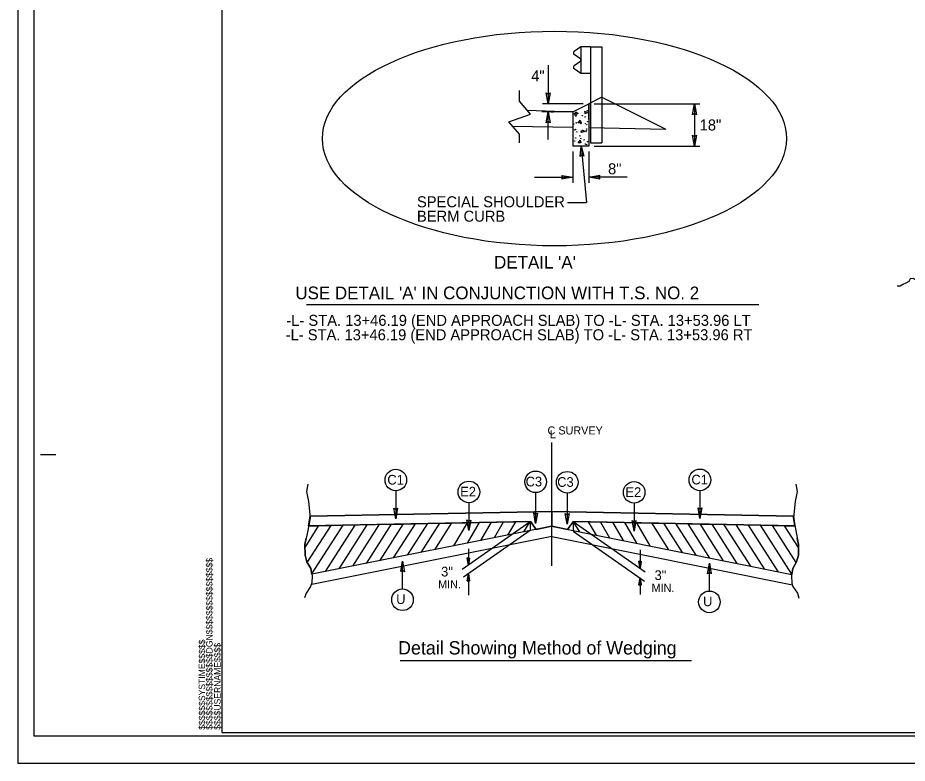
# Model space of a CAD drawing. Extents: x 573711 to 575883, y -54585 to -53485.
# Drawn here: x 573711 to 574439, y -54585 to -53975 of the extents above; entities that cross this region are included whole.
import ezdxf

# ---------------------------------------------------------------- set-up
doc = ezdxf.new("R2010")
doc.units = 0
for name, color, linetype in [('Old_Level_1', 7, 'Continuous'), ('Old_Level_11', 7, 'Continuous'), ('Old_Level_20', 7, 'Continuous'), ('Old_Level_21', 7, 'Continuous'), ('Prop Dimension', 7, 'Continuous'), ('Prop Shade Medium', 7, 'Continuous'), ('Prop Terminator CELL', 7, 'Continuous'), ('Sheet Cutting Line CELL', 7, 'Continuous'), ('Sheet Plot Border Inside CELL', 7, 'Continuous'), ('Sheet Plot Border Outside CELL', 7, 'Continuous'), ('Sheet Typical CELL', 7, 'Continuous'), ('Typical Curb CELL', 7, 'Continuous'), ('Typical Guardrail CELL', 7, 'Continuous'), ('Typical Pavement Slope CELL', 7, 'Continuous'), ('Typical Terminator CELL', 7, 'Continuous'), ('Typical Text Asphalt at Bridge Approach CELL', 7, 'Continuous'), ('Typical Text General CELL', 7, 'Continuous'), ('Typical Text Label CELL', 7, 'Continuous')]:
    doc.layers.add(name, color=color, linetype=linetype)

msp = doc.modelspace()

# ---------------------------------------------------------------- linework, layer by layer
at = {"layer": 'Old_Level_1'}
for p, q in [((574145.08, -54014.19), (574145.08, -54045.69)), ((574173.79, -54045.69), (574140.58, -54045.69)), ((574178.29, -54045.69), (574178.29, -54080.26)), ((574182.79, -54045.69), (574269.3, -54045.69)), ((574264.8, -54045.69), (574264.8, -54080.26)), ((574165.39, -54052.14), (574139.8, -54052.14)), ((574145.08, -54074.83), (574145.08, -54052.14)), ((574147.57, -54052.14), (574149.58, -54052.14)), ((574165.39, -54052.14), (574165.39, -54080.26)), ((574165.39, -54084.76), (574165.39, -54110.24)), ((574178.29, -54084.76), (574178.29, -54110.24)), ((574182.79, -54080.26), (574269.3, -54080.26)), ((574133.89, -54105.74), (574165.39, -54105.74)), ((574209.79, -54105.74), (574178.29, -54105.74)), ((574148.08, -54423.57), (574148.09, -54322.78)), ((574078.84, -54388.35), (574067.76, -54407.32)), ((574088.71, -54388.14), (574078.83, -54405.11)), ((574098.48, -54387.95), (574089.75, -54402.92)), ((574108.33, -54387.98), (574100.9, -54400.69)), ((574118.26, -54387.47), (574111.81, -54398.51)), ((574165.69, -54387.39), (574224.51, -54428.59)), ((574177.89, -54387.48), (574184.34, -54398.52)), ((574187.82, -54387.98), (574195.25, -54400.7)), ((574197.67, -54387.96), (574206.41, -54402.94)), ((574207.44, -54388.15), (574217.33, -54405.12)), ((574217.32, -54388.36), (574228.39, -54407.34)), ((574148, -54399.67), (573951.67, -54438.92)), ((574130.47, -54394.78), (574075.92, -54432.96)), ((574148.15, -54399.67), (574344.92, -54439.05)), ((574165.69, -54395.26), (574223.87, -54436)), ((574079.83, -54409.67), (574079.83, -54422.93)), ((574220.31, -54410.44), (574220.31, -54425.64)), ((574079.83, -54422.93), (574078.81, -54417.11)), ((574079.83, -54417.87), (574078.81, -54417.11)), ((574079.83, -54422.93), (574078.95, -54417.22)), ((574079.1, -54417.33), (574079.83, -54422.93)), ((574079.83, -54422.93), (574079.25, -54417.43)), ((574079.4, -54417.54), (574079.83, -54422.93)), ((574079.83, -54422.93), (574079.54, -54417.65)), ((574079.69, -54417.76), (574079.83, -54422.93)), ((574079.83, -54422.93), (574080.87, -54417.11)), ((574080.87, -54417.11), (574079.83, -54417.87)), ((574080.72, -54417.22), (574079.83, -54422.93)), ((574079.83, -54422.93), (574080.56, -54417.33)), ((574080.42, -54417.43), (574079.83, -54422.93)), ((574079.83, -54422.93), (574080.27, -54417.54)), ((574080.12, -54417.65), (574079.83, -54422.93)), ((574079.83, -54422.93), (574079.98, -54417.76)), ((574079.83, -54417.87), (574079.83, -54422.93)), ((574220.31, -54425.64), (574219.29, -54419.83)), ((574220.31, -54420.58), (574219.29, -54419.83)), ((574220.31, -54425.64), (574219.43, -54419.93)), ((574219.58, -54420.04), (574220.31, -54425.64)), ((574220.31, -54425.64), (574219.72, -54420.15)), ((574219.87, -54420.26), (574220.31, -54425.64)), ((574220.31, -54425.64), (574220.01, -54420.36)), ((574220.16, -54420.47), (574220.31, -54425.64)), ((574220.31, -54425.64), (574221.34, -54419.83)), ((574221.34, -54419.83), (574220.31, -54420.58)), ((574221.18, -54419.93), (574220.31, -54425.64)), ((574220.31, -54425.64), (574221.04, -54420.04)), ((574220.89, -54420.15), (574220.31, -54425.64)), ((574220.31, -54425.64), (574220.75, -54420.26)), ((574220.6, -54420.36), (574220.31, -54425.64)), ((574220.31, -54425.64), (574220.46, -54420.47)), ((574220.31, -54420.58), (574220.31, -54425.64)), ((574079.83, -54430.23), (574078.81, -54436.04)), ((574078.81, -54436.04), (574079.83, -54435.29)), ((574078.95, -54435.93), (574079.83, -54430.23)), ((574079.83, -54430.23), (574079.1, -54435.83)), ((574079.24, -54435.71), (574079.83, -54430.23)), ((574079.83, -54430.23), (574079.4, -54435.61)), ((574079.54, -54435.51), (574079.83, -54430.23)), ((574079.83, -54430.23), (574079.69, -54435.4)), ((574079.83, -54430.23), (574079.83, -54447.48)), ((574079.83, -54430.23), (574080.86, -54436.04)), ((574079.83, -54435.29), (574079.83, -54430.23)), ((574079.98, -54435.4), (574079.83, -54430.23)), ((574079.83, -54430.23), (574080.12, -54435.51)), ((574080.27, -54435.61), (574079.83, -54430.23)), ((574079.83, -54430.23), (574080.41, -54435.71)), ((574080.56, -54435.83), (574079.83, -54430.23)), ((574079.83, -54430.23), (574080.72, -54435.93)), ((574079.83, -54435.29), (574080.86, -54436.04)), ((574220.31, -54433.51), (574219.28, -54439.33)), ((574219.43, -54439.21), (574220.31, -54433.51)), ((574220.31, -54433.51), (574219.57, -54439.11)), ((574219.72, -54439), (574220.31, -54433.51)), ((574220.31, -54433.51), (574219.87, -54438.89)), ((574220.01, -54438.79), (574220.31, -54433.51)), ((574220.31, -54433.51), (574220.16, -54438.68)), ((574220.31, -54433.51), (574220.31, -54447.11)), ((574220.31, -54433.51), (574221.33, -54439.33)), ((574220.31, -54438.57), (574220.31, -54433.51)), ((574220.45, -54438.68), (574220.31, -54433.51)), ((574220.31, -54433.51), (574220.6, -54438.79)), ((574220.75, -54438.89), (574220.31, -54433.51)), ((574220.31, -54433.51), (574220.89, -54439)), ((574221.04, -54439.11), (574220.31, -54433.51)), ((574220.31, -54433.51), (574221.18, -54439.21)), ((574219.28, -54439.33), (574220.31, -54438.57)), ((574220.31, -54438.57), (574221.33, -54439.33))]:
    msp.add_line(p, q, dxfattribs=at)
for points in [[(574469.08, -54191.1), (574459.47, -54192.29), (574457.07, -54192.29), (574453.46, -54192.29), (574451.05, -54192.29), (574448.65, -54191.1), (574446.25, -54189.89), (574443.84, -54188.68), (574441.44, -54188.69), (574440.24, -54191.1), (574437.83, -54192.3), (574435.43, -54193.5), (574433.03, -54194.7), (574430.62, -54194.7)], [(573948.42, -54356.87), (573947.37, -54362.66), (573948.95, -54370.9), (573950.35, -54384.24), (573948.42, -54394.77), (573946.14, -54406.17), (573946.32, -54414.77), (573947.72, -54420.21), (573950.88, -54425.65), (573951.93, -54431.62), (573951.75, -54437.58), (573950.7, -54440.39), (573947.02, -54446.01), (573945.79, -54449.87)], [(574347.73, -54356.9), (574348.79, -54362.7), (574347.21, -54370.94), (574345.8, -54384.28), (574347.73, -54394.81), (574350.01, -54406.21), (574349.84, -54414.81), (574348.42, -54420.24), (574345.27, -54425.69), (574344.22, -54431.65), (574344.39, -54437.62), (574345.44, -54440.43), (574349.12, -54446.05), (574350.35, -54449.91)], [(573946.19, -54408.47), (573957.58, -54390.7)], [(573948.04, -54420.75), (573967.42, -54390.5)], [(573951.68, -54430.22), (573977.25, -54390.31)], [(573962.93, -54428.28), (573987.23, -54390.35)], [(573974.06, -54426.06), (573997.07, -54390.15)], [(573985.2, -54423.83), (574006.9, -54389.96)], [(573996.36, -54421.6), (574016.94, -54389.49)], [(574007.5, -54419.37), (574026.78, -54389.29)], [(574018.64, -54417.14), (574036.62, -54389.09)], [(574030.03, -54414.87), (574046.69, -54388.88)], [(574041.17, -54412.64), (574056.52, -54388.68)], [(574052.31, -54410.41), (574066.36, -54388.48)], [(574243.85, -54410.43), (574229.8, -54388.5)], [(574254.99, -54412.66), (574239.64, -54388.7)], [(574266.13, -54414.89), (574249.47, -54388.9)], [(574277.51, -54417.17), (574259.54, -54389.11)], [(574288.65, -54419.4), (574269.38, -54389.31)], [(574299.79, -54421.63), (574279.22, -54389.51)], [(574310.94, -54423.86), (574289.24, -54389.99)], [(574322.08, -54426.09), (574299.08, -54390.18)], [(574333.22, -54428.32), (574308.92, -54390.38)], [(574344.46, -54430.26), (574318.89, -54390.34)], [(574348.11, -54420.79), (574328.73, -54390.53)], [(574349.96, -54408.52), (574338.57, -54390.73)], [(573951.73, -54430.52), (573950.88, -54425.65), (573947.72, -54420.21), (573946.32, -54414.77), (573946.14, -54406.17), (573947.2, -54400.89)], [(574344.41, -54430.56), (574345.27, -54425.69), (574348.42, -54420.24), (574349.84, -54414.81), (574350.01, -54406.21), (574348.95, -54400.92)]]:
    msp.add_lwpolyline(points, dxfattribs=at)
msp.add_ellipse((574150.25, -54074.07), major_axis=(189.85, 0), ratio=0.462267, dxfattribs=at)
at = {"layer": 'Old_Level_11'}
for p, q in [((574020.45, -54362.22), (574020.45, -54385.06)), ((574134.86, -54363.71), (574134.85, -54389.04)), ((574269.29, -54362.1), (574269.28, -54384.93)), ((574160.7, -54364.06), (574160.7, -54389.4)), ((574080.24, -54371.96), (574080.24, -54394.8)), ((574215.46, -54372.32), (574215.46, -54395.15)), ((573949.13, -54390.92), (573950.26, -54382.97)), ((574148.07, -54379.04), (573950.26, -54382.97)), ((573950.26, -54382.97), (574148.07, -54379.04)), ((574148.07, -54379.04), (574345.9, -54383.01)), ((574148.09, -54379.04), (574345.9, -54383.01)), ((574345.9, -54383.01), (574347.03, -54390.96)), ((574130.72, -54387.31), (573949.13, -54390.92)), ((574130.72, -54387.31), (573949.13, -54390.92)), ((574148.37, -54391.2), (573951.74, -54430.52)), ((574130.49, -54387.46), (574074.76, -54426.49)), ((574125.1, -54395.77), (574130.47, -54387.38)), ((574130.47, -54387.38), (574130.47, -54394.78)), ((574135.16, -54393.83), (574130.72, -54387.31)), ((574130.72, -54387.52), (574135.16, -54393.83)), ((574147.78, -54391.2), (574135.16, -54393.83)), ((574147.78, -54391.2), (574344.41, -54430.56)), ((574160.99, -54393.83), (574147.78, -54391.2)), ((574165.58, -54387.31), (574160.99, -54393.83)), ((574165.58, -54387.31), (574160.99, -54393.83)), ((574165.28, -54387.46), (574165.57, -54387.47)), ((574165.58, -54387.31), (574347.03, -54390.96)), ((574347.03, -54390.96), (574165.58, -54387.31)), ((574171.06, -54395.77), (574165.69, -54387.39)), ((574165.69, -54387.39), (574165.69, -54394.79)), ((574025.92, -54442.47), (574025.93, -54419.63)), ((574277.02, -54444.26), (574277.03, -54421.42)), ((574262.32, -54501.4), (574024.05, -54501.37))]:
    msp.add_line(p, q, dxfattribs=at)
for points in [[(574021.95, -54376.37), (574020.45, -54385.06), (574018.9, -54376.32), (574020.45, -54377.43)], [(574270.78, -54376.25), (574269.28, -54384.93), (574267.74, -54376.2), (574269.28, -54377.31)], [(574136.35, -54380.36), (574134.85, -54389.04), (574133.31, -54380.31), (574134.85, -54381.42)], [(574162.2, -54380.71), (574160.7, -54389.4), (574159.15, -54380.66), (574160.7, -54381.77)], [(574081.74, -54386.11), (574080.24, -54394.8), (574078.69, -54386.06), (574080.24, -54387.17)], [(574216.95, -54386.47), (574215.46, -54395.15), (574213.91, -54386.42), (574215.46, -54387.53)], [(574024.43, -54428.32), (574025.93, -54419.63), (574027.47, -54428.37), (574025.93, -54427.26)], [(574275.53, -54430.11), (574277.03, -54421.42), (574278.57, -54430.16), (574277.03, -54429.05)]]:
    msp.add_lwpolyline(points, close=True, dxfattribs=at)
for centre in [(574020.45, -54353.39), (574134.86, -54354.87), (574160.7, -54355.22), (574269.28, -54353.27), (574080.24, -54363.13), (574215.46, -54363.48), (574025.92, -54451.3), (574277.02, -54453.09)]:
    msp.add_circle(centre, 8.84, dxfattribs=at)
at = {"layer": 'Prop Dimension'}
for p in [(574172.01, -54080.26), (574160.82, -54126.44)]:
    msp.add_line(p, (574176.51, -54126.44), dxfattribs=at)
at = {"layer": 'Prop Shade Medium'}
for points in [[(574066.29, -54388.59), (574088.71, -54388.15), (574118.2, -54387.56), (574130.72, -54387.31), (574135.16, -54393.83), (574147.78, -54391.2), (574148.08, -54391.26), (574148.08, -54391.26), (574148.08, -54379.04), (574148.07, -54379.04), (573950.26, -54382.97), (573950.24, -54383.16), (573950.35, -54384.24), (573949.16, -54390.72), (573949.13, -54390.92), (573957.54, -54390.76), (573967.38, -54390.56), (573977.22, -54390.36), (574016.89, -54389.57), (574026.72, -54389.38), (574036.56, -54389.18), (574046.62, -54388.98), (574056.45, -54388.79), (574066.29, -54388.59)], [(574229.87, -54388.61), (574239.7, -54388.8), (574249.54, -54389), (574259.6, -54389.2), (574269.44, -54389.4), (574279.27, -54389.6), (574318.93, -54390.39), (574328.77, -54390.59), (574338.61, -54390.79), (574347.02, -54390.96), (574345.8, -54384.28), (574345.92, -54383.17), (574345.9, -54383.01), (574148.09, -54379.04), (574148.08, -54379.04), (574148.08, -54391.26), (574148.08, -54391.26), (574160.99, -54393.83), (574165.47, -54387.47), (574165.58, -54387.31), (574177.95, -54387.56), (574207.44, -54388.15), (574207.44, -54388.15), (574207.44, -54388.15), (574229.87, -54388.61)]]:
    msp.add_lwpolyline(points, dxfattribs=at)
at = {"layer": 'Prop Terminator CELL'}
for points in [[(574146.63, -54036.69), (574145.08, -54045.69), (574143.48, -54036.64), (574145.08, -54037.79)], [(574263.25, -54054.69), (574264.8, -54045.69), (574266.4, -54054.74), (574264.8, -54053.59)], [(574143.53, -54061.14), (574145.08, -54052.14), (574146.68, -54061.19), (574145.08, -54060.04)], [(574266.35, -54071.26), (574264.8, -54080.26), (574263.2, -54071.21), (574264.8, -54072.36)], [(574156.39, -54104.19), (574165.39, -54105.74), (574156.34, -54107.34), (574157.49, -54105.74)], [(574187.29, -54107.29), (574178.29, -54105.74), (574187.34, -54104.14), (574186.19, -54105.74)]]:
    msp.add_lwpolyline(points, close=True, dxfattribs=at)
at = {"layer": 'Sheet Cutting Line CELL'}
for p, q in [((573711.13, -53485.01), (573711.13, -54585.01)), ((573711.13, -54585.01), (575395.13, -54585.01))]:
    msp.add_line(p, q, dxfattribs=at)
at = {"layer": 'Sheet Plot Border Inside CELL'}
msp.add_lwpolyline([(575390.63, -53507.46), (573724.13, -53507.46), (573724.13, -54562.56), (575390.63, -54562.56)], close=True, dxfattribs=at)
at = {"layer": 'Sheet Plot Border Outside CELL'}
msp.add_lwpolyline([(575395.13, -53485.01), (573711.13, -53485.01), (573711.13, -54585.01), (575395.13, -54585.01)], close=True, dxfattribs=at)
at = {"layer": 'Sheet Typical CELL'}
for p, q in [((573729.63, -54332.51), (573742.13, -54332.51)), ((573878.13, -54560.01), (573878.13, -54560.01)), ((573878.13, -54560.01), (573878.13, -54560.01)), ((573878.13, -54560.01), (573878.13, -54560.01)), ((573878.13, -54560.01), (573878.13, -54560.01)), ((573878.13, -54560.01), (573878.13, -54560.01)), ((573878.13, -54560.01), (573878.13, -54560.01))]:
    msp.add_line(p, q, dxfattribs=at)
msp.add_lwpolyline([(575378.13, -53510.01), (573878.13, -53510.01), (573878.13, -54560.01), (575378.13, -54560.01)], close=True, dxfattribs=at)
msp.add_lwpolyline([(573915.63, -54560.01), (573915.63, -54560.01)], dxfattribs=at)
at = {"layer": 'Typical Curb CELL'}
for p, q in [((574127.89, -54050.8), (574165.39, -54052.14)), ((574165.39, -54052.14), (574178.29, -54045.69)), ((574178.29, -54058.39), (574178.29, -54045.69)), ((574166.56, -54054.39), (574167.73, -54052.24)), ((574169.67, -54053.65), (574166.56, -54054.39)), ((574167.73, -54052.24), (574169.67, -54053.65)), ((574174.71, -54051.95), (574175.02, -54053.64)), ((574177.6, -54052.79), (574174.71, -54051.95)), ((574175.02, -54053.64), (574177.6, -54052.79)), ((574169.75, -54061.23), (574171.35, -54058.98)), ((574172, -54061.11), (574169.75, -54061.23)), ((574171.35, -54058.98), (574172, -54061.11)), ((574172.09, -54069.06), (574173.27, -54066.91)), ((574175.2, -54068.32), (574172.09, -54069.06)), ((574173.27, -54066.91), (574175.2, -54068.32)), ((574169.66, -54077.71), (574171.28, -54075.46)), ((574171.92, -54077.59), (574169.66, -54077.71)), ((574171.28, -54075.46), (574171.92, -54077.59)), ((574178.29, -54080.26), (574165.39, -54080.26))]:
    msp.add_line(p, q, dxfattribs=at)
for centre in [(574177.07, -54051.18), (574166.7, -54053.36), (574167.23, -54055.26), (574167.86, -54055.77), (574168.18, -54054.82), (574173, -54055.36), (574175.25, -54056.31), (574166.23, -54062.07), (574168.04, -54061.22), (574169.79, -54061.04), (574172.04, -54061.99), (574175.68, -54061.99), (574176.73, -54062.63), (574177.35, -54060.25), (574166.77, -54067.17), (574167.71, -54066.6), (574168.58, -54068.76), (574171.09, -54071.87), (574172.23, -54068.03), (574176.08, -54068.33), (574176.4, -54067.38), (574176.59, -54066.27), (574166.89, -54076.08), (574167.6, -54073.73), (574171.97, -54074.04), (574174.48, -54075.13), (574175.6, -54078.47), (574176.65, -54079.11), (574177.27, -54076.74)]:
    msp.add_circle(centre, 0.15, dxfattribs=at)
at = {"layer": 'Typical Guardrail CELL'}
for p, q in [((574171.83, -53999.08), (574166.4, -54002.89)), ((574171.83, -53999.08), (574171.83, -54020.83)), ((574179.79, -53999.08), (574171.83, -53999.08)), ((574179.79, -53999.08), (574179.79, -54045.69)), ((574179.79, -53999.08), (574189.11, -53999.08)), ((574189.11, -53999.08), (574189.11, -54045.69)), ((574171.83, -54009.08), (574166.4, -54005.27)), ((574171.83, -54010.83), (574166.4, -54014.64)), ((574171.83, -54009.96), (574171.83, -54009.08)), ((574171.83, -54009.96), (574171.83, -54010.83)), ((574171.83, -54020.83), (574166.4, -54017.02)), ((574179.79, -54020.83), (574171.83, -54020.83)), ((574189.11, -54040.28), (574178.29, -54045.69)), ((574189.11, -54040.28), (574241.27, -54066.36)), ((574179.79, -54045.69), (574179.79, -54077.49)), ((574189.11, -54045.69), (574189.11, -54077.49)), ((574179.79, -54077.49), (574189.11, -54077.49))]:
    msp.add_line(p, q, dxfattribs=at)
for centre, start, end in [((574167.23, -54004.08), 125.00297, 235.0112), ((574167.23, -54015.83), 125.0059, 235.0366)]:
    msp.add_arc(centre, 1.46, start, end, dxfattribs=at)
at = {"layer": 'Typical Pavement Slope CELL'}
for p, q in [((574115.81, -54063.85), (574165.39, -54064.84)), ((574178.29, -54065.1), (574241.27, -54066.36))]:
    msp.add_line(p, q, dxfattribs=at)
at = {"layer": 'Typical Terminator CELL'}
msp.add_lwpolyline([(574171.38, -54088.8), (574172.01, -54080.26), (574174.32, -54088.56), (574172.73, -54087.63)], close=True, dxfattribs=at)
at = {"layer": 'Typical Text Asphalt at Bridge Approach CELL'}
msp.add_lwpolyline([(574121.64, -54077.49), (574121.64, -54070.62), (574112.84, -54060.4), (574130.77, -54054.16), (574121.64, -54043.52), (574121.62, -54034.8)], dxfattribs=at)
at = {"layer": 'Typical Text Label CELL'}
msp.add_line((573947.29, -54209.87), (574317.43, -54209.87), dxfattribs=at)

# ---------------------------------------------------------------- texts
at = {"layer": 'Old_Level_1'}
for s, p in [('4"', (574131.21, -54027.36)), ('18"', (574269.08, -54067.48)), ('8"', (574194.11, -54103.31))]:
    msp.add_text(s, height=9, dxfattribs=at).set_placement(p)
for s, height, p in [('C SURVEY ', 6.609, (574144.59, -54316.12)), ('L', 6.61, (574146.52, -54319.22))]:
    msp.add_text(s, height=height, rotation=359.99465, dxfattribs=at).set_placement(p)
at = {"layer": 'Old_Level_20'}
for s, height, p in [('C1', 7.908, (574013.51, -54357.12)), ('C1', 7.908, (574262.34, -54357)), ('C3', 7.908, (574126.64, -54358.61)), ('C3', 7.908, (574152.48, -54358.96)), ('E2', 7.908, (574073.11, -54366.86)), ('E2', 7.908, (574208.33, -54367.22)), ('3"', 7.908, (574057.51, -54432.28)), ('3"', 7.908, (574232.17, -54435.16)), ('U', 7.91, (574020.74, -54454.8)), ('U', 7.91, (574271.84, -54456.59))]:
    msp.add_text(s, height=height, rotation=359.99465, dxfattribs=at).set_placement(p)
at = {"layer": 'Old_Level_21'}
for s, height, p in [('MIN.', 6.609, (574055.09, -54442)), ('MIN.', 6.609, (574229.75, -54444.89)), ('Detail Showing Method of Wedging', 10.9083, (574022.34, -54496.08))]:
    msp.add_text(s, height=height, rotation=359.99465, dxfattribs=at).set_placement(p)
at = {"layer": 'Sheet Typical CELL'}
for s, p in [('$$$$$$$$$$$$$$$$DGN$$$$$$$$$$$$$$$$', (573870.48, -54557.65)), ('$$$$$$SYSTIME$$$$$', (573864.43, -54557.65)), ('$$$$USERNAME$$$$', (573877.06, -54557.64))]:
    msp.add_text(s, height=5.25, rotation=90, dxfattribs=at).set_placement(p)
at = {"layer": 'Typical Text General CELL'}
for s, p in [('SPECIAL SHOULDER', (574037.75, -54130.29)), ('BERM CURB', (574037.75, -54142.09))]:
    msp.add_text(s, height=9, dxfattribs=at).set_placement(p)
at = {"layer": 'Typical Text Label CELL'}
for s, height, p in [("   DETAIL 'A'", 10.3693, (574089.29, -54180.42)), ("   USE DETAIL 'A' IN CONJUNCTION WITH T.S. NO. 2", 10.3693, (573926.7, -54205.52)), ('-L- STA. 13+46.19 (END APPROACH SLAB) TO -L- STA. 13+53.96 LT', 9, (573930.88, -54227.28)), ('-L- STA. 13+46.19 (END APPROACH SLAB) TO -L- STA. 13+53.96 RT', 9, (573930.35, -54239.08))]:
    msp.add_text(s, height=height, dxfattribs=at).set_placement(p)

doc.saveas('drawing.dxf')
